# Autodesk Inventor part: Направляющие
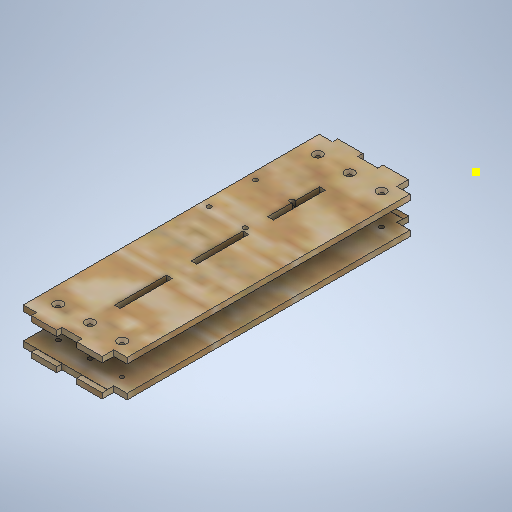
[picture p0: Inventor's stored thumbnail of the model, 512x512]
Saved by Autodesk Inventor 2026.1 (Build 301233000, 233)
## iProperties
Created: 2025-12
Part Number: Направляющие
Material: Типовые
Document SubType Name: Modeling
Designer: Yury Melnikov
Density: 1 g/cm^3
Appearance: По умолчанию
Author: Yury Melnikov
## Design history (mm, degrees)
sketch "Эскиз1"
  geometry: L1 (0, 0)-(16, 0); L2 (16, 0)-(16, -200); L3 (16, -200)-(0, -200); L4 (0, -200)-(0, 0); 1 further point
  constraints: 8 end point, 2 parallel, 1 coincident, 1 horizontal, 1 perpendicular
  dimensions: "d0" = 16 distance of L2.end L3.end; "d1" = 200 distance of L1.end L2.end
extrude "Выдавливание1" new body sketch "Эскиз1" distance "d2" = 200; taper "d3" = 0 deg
sketch "Эскиз2"
  geometry: 1 further point
sketch "Эскиз3"
  geometry: L1 (0, 0)-(0, -200) reference; L2 (-16, -200)-(-16, 0) reference; L3 (-28.3, -33.725)-(12.3, -10.284); L4 (12.3, -10.284)-(12.3, -57.165); L5 (12.3, -57.165)-(-28.3, -33.725); C1 r 12.3 at (-28.3, -33.725); C2 r 12.3 at (12.3, -10.284); C3 r 12.3 at (12.3, -57.165); 1 further point
  constraints: 6 end point, 3 centre point, 3 coincident, 2 equal radius, 2 tangent, 1 vertical, 7 other
  dimensions: "d4" = 24.6 diameter of C2
extrude "Выдавливание2" new body sketch "Эскиз3" distance "d5" = 11; taper "d6" = 0 deg
sketch "Эскиз4"
  geometry: C1 r 12.3 at (0, 0) reference; C2 r 12.3 at (40.6, 23.44) reference; C3 r 12.3 at (40.6, -23.44) reference; C4 r 4 at (0, 0); C5 r 4 at (40.6, 23.44); C6 r 4 at (40.6, -23.44); 1 further point
  constraints: 3 centre point, 3 coincident, 2 equal radius
  dimensions: "d7" = 8 diameter of C5
extrude "Выдавливание3" join sketch "Эскиз4" distance "d8" = 6; taper "d9" = 0 deg
sketch "Эскиз5"
  geometry: L1 (-6.15, 10.652)-(34.45, 34.093); L2 (52.9, 23.44)-(52.9, -23.44); L3 (34.45, -34.093)-(-6.15, -10.652); A1 r 12.3 centre (40.6, -23.44) between (34.45, -34.093) and (52.9, -23.44) reference; A2 r 12.3 centre (40.6, 23.44) between (52.9, 23.44) and (34.45, 34.093) reference; A3 r 12.3 centre (0, 0) between (-6.15, -10.652) and (-6.15, 10.652) reference; 1 further point
  constraints: 6 end point, 6 point on circle, 6 tangent
extrude "Выдавливание4" new body sketch "Эскиз5" distance "d10" = 4; taper "d11" = 0 deg
sketch "Эскиз6"
  geometry: L1 (0, 0)-(40.6, 23.44); L2 (40.6, 23.44)-(40.6, -23.44); L3 (40.6, -23.44)-(0, 0); L4 (35.6, 23.44)-(2.5, 4.33); L5 (2.5, -4.33)-(35.6, -23.44); L6 (43.1, -19.11)-(43.1, 19.11); L7 (38.1, 19.11)-(5, 0); L8 (5, 0)-(38.1, -19.11); L9 (38.1, -19.11)-(38.1, 19.11); C1 r 12.3 at (40.6, 23.44) reference; C2 r 12.3 at (40.6, -23.44) reference; C3 r 12.3 at (0, 0) reference; C4 r 1.6 at (0, 0); C5 r 1.6 at (40.6, 23.44); C6 r 1.6 at (40.6, -23.44); A1 r 5 centre (40.6, 23.44) between (43.1, 19.11) and (35.6, 23.44); A2 r 5 centre (0, 0) between (2.5, 4.33) and (2.5, -4.33); A3 r 5 centre (40.6, -23.44) between (35.6, -23.44) and (43.1, -19.11); 3 further points
  constraints: 18 end point, 8 coincident, 6 centre point, 6 point on circle, 2 equal length, 2 equal radius, 2 parallel, 13 other
  dimensions: "d12" = 2.5 distance between parallel lines of L1 L7; "d13" = 2.5 distance between parallel lines of L1 L4 (= d12); "d14" = 3.2 diameter of C4 (derived); "d15" = 3.2 diameter of C5 (derived); "d16" = 3.2 diameter of C6
extrude "Выдавливание5" join sketch "Эскиз6" distance "d17" = 5; taper "d18" = 0 deg
sketch "Эскиз7"
  geometry: C1 r 1.6 at (40.6, 23.44) reference; C2 r 1.6 at (0, 0) reference; C3 r 1.6 at (40.6, -23.44) reference; 1 further point
  node "Спроецированная петля5"
  node "Спроецированная петля6"
  node "Спроецированная петля7"
fillet "Сопряжение1" dims "d19" = 5
chamfer "Фаска1" distance "d20" = 2; stored, may be unused: second distance "d21" = 2, angle "d22" = 45 deg
extrude "Выдавливание6" cut sketch "Эскиз7" distance "d23" = 5; taper "d24" = 0 deg
sketch "Эскиз8"
  geometry: L1 (4.478, 5.472)-(33.622, 22.298) reference; L2 (43.1, 16.826)-(43.1, -16.826) reference; L3 (33.622, -22.298)-(4.478, -5.472) reference; L4 (34.45, 34.093)-(-6.15, 10.652) reference; L5 (-6.15, -10.652)-(34.45, -34.093) reference; L6 (52.9, -23.44)-(52.9, 23.44) reference; L7 (30, -82.992)-(34, -82.992); L8 (28.3, 33.725)-(28.3, -166.275) reference; L9 (142.9, -11.74)-(142.9, -38.74); L10 (139.9, -41.74)-(46.638, -41.74); L11 (35.571, -38.399)-(-6.806, -10.245); L12 (34.45, 34.093)-(-6.15, 10.652) reference; L13 (-6.15, 10.652)-(32.359, 35.974); L14 (141.217, -9.045)-(47.187, 36.917); A1 r 5 centre (1.978, -9.802) between (4.478, -5.472) and (0.989, -4.901) reference; A2 r 5 centre (0, 0) between (0.989, 4.901) and (0.989, -4.901) reference; A3 r 5 centre (1.978, 9.802) between (0.989, 4.901) and (4.478, 5.472) reference; A4 r 5 centre (31.122, 26.628) between (33.622, 22.298) and (35.861, 25.034) reference; A5 r 5 centre (40.6, 23.44) between (44.35, 20.133) and (35.861, 25.034) reference; A6 r 5 centre (48.1, 16.826) between (44.35, 20.133) and (43.1, 16.826) reference; A7 r 5 centre (48.1, -16.826) between (43.1, -16.826) and (44.35, -20.133) reference; A8 r 5 centre (40.6, -23.44) between (35.861, -25.034) and (44.35, -20.133) reference; A9 r 5 centre (31.122, -26.628) between (35.861, -25.034) and (33.622, -22.298) reference; A10 r 12.3 centre (40.6, 23.44) between (52.9, 23.44) and (34.45, 34.093) reference; A11 r 12.3 centre (0, 0) between (-6.15, 10.652) and (-6.15, -10.652) reference; A12 r 12.3 centre (40.6, -23.44) between (34.45, -34.093) and (52.9, -23.44) reference; A13 r 12.3 centre (0, 0) between (-6.15, 10.652) and (-6.15, -10.652) reference; A14 r 12.3 centre (40.6, 23.44) between (52.9, 23.44) and (34.45, 34.093) reference; A15 r 20 centre (46.638, -21.74) between (35.571, -38.399) and (46.638, -41.74); A16 r 3 centre (139.9, -11.74) between (142.9, -11.74) and (141.217, -9.045); A17 r 3 centre (139.9, -38.74) between (139.9, -41.74) and (142.9, -38.74); A18 r 15 centre (40.6, 23.44) between (26.541, 18.21) and (28.3, 14.855); A19 r 15 centre (40.6, 23.44) between (47.187, 36.917) and (32.359, 35.974); 6 further points
  constraints: 14 point on circle, 12 end point, 9 tangent, 7 point on line, 5 centre point, 1 coincident, 1 horizontal, 1 vertical, 1 vertical alignment
  dimensions: "d40" = 8 distance of point (142.9, -33.74) point (142.9, -41.74); "d41" = 90 distance from line of point (142.9, -41.74) L6; "d42" = 6 distance edge to line of A12 L10; "d43" = 20 radius of A15; "d44" = 3 radius of A16; "d45" = 3 radius of A17 (= d44); "d61" = 15 radius of A19; "d62" = 30 distance from line of L10 L9.start
extrude "Выдавливание7" new body sketch "Эскиз8" distance "d26" = 4; taper "d27" = 0 deg
node "РабПлоскость1"
sketch "Эскиз11"
  geometry: L1 (-6.806, -10.245)-(35.571, -38.399) reference; L2 (46.638, -41.74)-(139.9, -41.74) reference; L3 (142.9, -38.74)-(142.9, -11.74) reference; L4 (33.622, -22.298)-(4.478, -5.472) reference; L5 (4.478, 5.472)-(33.622, 22.298) reference; L6 (43.1, 16.826)-(43.1, -16.826) reference; L7 (30.967, -35.34)-(142.9, -35.34); L8 (37.92, -39.74)-(142.728, -39.74); L9 (77.92, -35.34)-(97.92, -35.34); L10 (97.92, -35.34)-(97.92, -39.74); L11 (97.92, -39.74)-(77.92, -39.74); L12 (77.92, -39.74)-(77.92, -35.34); L13 (112.9, -35.34)-(132.9, -35.34); L14 (132.9, -35.34)-(132.9, -39.74); L15 (132.9, -39.74)-(112.9, -39.74); L16 (112.9, -39.74)-(112.9, -35.34); L17 (32.359, 35.974)-(-6.15, 10.652) reference; L18 (141.217, -9.045)-(47.187, 36.917) reference; A1 r 12.3 centre (0, 0) between (-6.15, 10.652) and (-6.806, -10.245) reference; A2 r 20 centre (46.638, -21.74) between (35.571, -38.399) and (46.638, -41.74) reference; A3 r 3 centre (139.9, -38.74) between (139.9, -41.74) and (142.9, -38.74) reference; A4 r 3 centre (139.9, -11.74) between (142.9, -11.74) and (141.217, -9.045) reference; A5 r 5 centre (1.978, -9.802) between (4.478, -5.472) and (0.989, -4.901) reference; A6 r 5 centre (0, 0) between (0.989, 4.901) and (0.989, -4.901) reference; A7 r 5 centre (1.978, 9.802) between (0.989, 4.901) and (4.478, 5.472) reference; A8 r 5 centre (31.122, 26.628) between (33.622, 22.298) and (35.861, 25.034) reference; A9 r 5 centre (40.6, 23.44) between (44.35, 20.133) and (35.861, 25.034) reference; A10 r 5 centre (48.1, 16.826) between (44.35, 20.133) and (43.1, 16.826) reference; A11 r 5 centre (48.1, -16.826) between (43.1, -16.826) and (44.35, -20.133) reference; A12 r 5 centre (40.6, -23.44) between (35.861, -25.034) and (44.35, -20.133) reference; A13 r 5 centre (31.122, -26.628) between (35.861, -25.034) and (33.622, -22.298) reference; A14 r 15 centre (40.6, 23.44) between (47.187, 36.917) and (32.359, 35.974) reference; 1 further point
  constraints: 20 end point, 6 point on line, 4 horizontal, 4 parallel, 2 perpendicular, 2 point on circle
  dimensions: "d47" = 4.4 distance between parallel lines of L8 L7; "d48" = 2 distance between parallel lines of L2 L8; "d49" = 20 distance between parallel lines of L12 L10; "d50" = 20 distance between parallel lines of L14 L16; "d51" = 10 distance between parallel lines of L14 L3; "d52" = 40 distance from line of L8.start L12
extrude "Выдавливание9" cut sketch "Эскиз11" distance "d53" = 4; taper "d54" = 0 deg
chamfer "Фаска2" distance "d55" = 2; stored, may be unused: second distance "d56" = 2, angle "d57" = 45 deg
fillet "Сопряжение2" dims "d58" = 1
sketch "Эскиз14"
  geometry: L1 (-142.9, -35.34)-(-67.92, -35.34); L2 (-67.92, -35.34)-(-67.92, -39.74); L3 (-67.92, -39.74)-(-142.9, -39.74); L4 (-142.9, -39.74)-(-142.9, -35.34); L5 (-97.92, -35.34)-(-77.92, -35.34) reference; L6 (-77.92, -39.74)-(-97.92, -39.74) reference; L7 (-77.92, -35.34)-(-77.92, -39.74) reference; L8 (-142.9, -38.74)-(-142.9, -11.74) reference; 2 further points
  constraints: 8 end point, 3 collinear, 2 parallel, 1 horizontal, 1 midpoint, 1 perpendicular
  dimensions: "d63" = 10 distance from line of L2 point (-77.92, -37.54)
extrude "Выдавливание10" new body sketch "Эскиз14" distance "d65" = 228; taper "d66" = 0 deg
sketch "Эскиз15"
  geometry: L1 (3, 15)-(3, 11.4); L2 (3, 11.4)-(8, 6.4); L3 (8, 6.4)-(20, 6.4); L4 (20, 6.4)-(20, 3.4); L5 (20, 3.4)-(0, 3.4); L6 (0, 3.4)-(228, 3.4) reference; L7 (0, 3.4)-(0, 23); L8 (0, 23)-(20, 23); L9 (3, 15)-(8, 20); L10 (8, 20)-(20, 20); L11 (20, 20)-(20, 23); 5 further points; 1 other entity
  constraints: 20 end point, 4 equal length, 3 vertical, 2 horizontal, 2 perpendicular, 1 collinear, 1 other
  dimensions: "d67" = 3 distance of L3.end L4.end; "d76" = 3 distance between parallel lines of L7 L1 (derived); "d77" = 20 distance of L4.end L5.end; "d78" = 135 deg angle of L10 L9; "d79" = 5 horizontal distance of L1.start L9.end; "d108" = 4 distance of L7.end point (0, 27)
extrude "Выдавливание11" new body sketch "Эскиз15" stored distance "d69" = 128; taper "d70" = 0 deg
sketch "Эскиз16"
  geometry: L1 (67.92, -35.34)-(142.9, -35.34) reference; L2 (67.92, -39.74)-(67.92, -35.34) reference; L3 (142.9, -39.74)-(67.92, -39.74) reference; L4 (142.9, -35.34)-(142.9, -39.74) reference; L5 (132.9, -35.34)-(132.9, -39.74) reference; L6 (132.9, -39.74)-(112.9, -39.74) reference; L7 (112.9, -39.74)-(112.9, -35.34) reference; L8 (112.9, -35.34)-(132.9, -35.34) reference; L9 (97.92, -35.34)-(97.92, -39.74) reference; L10 (97.92, -39.74)-(77.92, -39.74) reference; L11 (77.92, -39.74)-(77.92, -35.34) reference; L12 (77.92, -35.34)-(97.92, -35.34) reference; L13 (-6.806, -10.245)-(35.571, -38.399) reference; L14 (46.638, -41.74)-(139.9, -41.74) reference; L15 (142.9, -38.74)-(142.9, -11.74) reference; L16 (141.217, -9.045)-(47.187, 36.917) reference; L17 (32.359, 35.974)-(-6.15, 10.652) reference; L18 (33.622, -22.298)-(4.478, -5.472) reference; L19 (4.478, 5.472)-(33.622, 22.298) reference; L20 (43.1, 16.826)-(43.1, -16.826) reference; L21 (97.72, -39.54)-(97.72, -35.54); L22 (97.72, -35.54)-(78.12, -35.54); L23 (78.12, -35.54)-(78.12, -39.54); L24 (78.12, -39.54)-(97.72, -39.54); L25 (113.1, -35.54)-(113.1, -39.54); L26 (113.1, -39.54)-(132.7, -39.54); L27 (132.7, -39.54)-(132.7, -35.54); L28 (132.7, -35.54)-(113.1, -35.54); A1 r 12.3 centre (0, 0) between (-6.15, 10.652) and (-6.806, -10.245) reference; A2 r 20 centre (46.638, -21.74) between (35.571, -38.399) and (46.638, -41.74) reference; A3 r 3 centre (139.9, -38.74) between (139.9, -41.74) and (142.9, -38.74) reference; A4 r 3 centre (139.9, -11.74) between (142.9, -11.74) and (141.217, -9.045) reference; A5 r 15 centre (40.6, 23.44) between (47.187, 36.917) and (32.359, 35.974) reference; A6 r 5 centre (1.978, -9.802) between (4.478, -5.472) and (0.989, -4.901) reference; A7 r 5 centre (0, 0) between (0.989, 4.901) and (0.989, -4.901) reference; A8 r 5 centre (1.978, 9.802) between (0.989, 4.901) and (4.478, 5.472) reference; A9 r 5 centre (31.122, 26.628) between (33.622, 22.298) and (35.861, 25.034) reference; A10 r 5 centre (40.6, 23.44) between (44.35, 20.133) and (35.861, 25.034) reference; A11 r 5 centre (48.1, 16.826) between (44.35, 20.133) and (43.1, 16.826) reference; A12 r 5 centre (48.1, -16.826) between (43.1, -16.826) and (44.35, -20.133) reference; A13 r 5 centre (40.6, -23.44) between (35.861, -25.034) and (44.35, -20.133) reference; A14 r 5 centre (31.122, -26.628) between (35.861, -25.034) and (33.622, -22.298) reference; 1 further point
  constraints: 16 end point, 6 other
  dimensions: "d71" = 0.2 distance between parallel lines of L9 L21; "d72" = 0.2 distance between parallel lines of L7 L25
extrude "Выдавливание12" join sketch "Эскиз16" stored distance "d73" = 228; taper "d74" = 0 deg
node "РабПлоскость2"
mirror "Зеркальное отражение2"
sketch "Эскиз17"
  geometry: L1 (15.8, 7.674)-(15.8, 4.326); L2 (15.8, 4.326)-(12.9, 2.651); L3 (12.9, 2.651)-(10, 4.326); L4 (10, 4.326)-(10, 7.674); L5 (10, 7.674)-(12.9, 9.349); L6 (12.9, 9.349)-(15.8, 7.674); L7 (12.9, 0.342)-(17.8, 3.171); L8 (17.8, 3.171)-(17.8, 8.829); L9 (17.8, 8.829)-(12.9, 11.658); L10 (12.9, 11.658)-(8, 8.829); L11 (8, 8.829)-(8, 3.171); L12 (8, 3.171)-(12.9, 0.342); L13 (0, 0)-(0, 12) reference; L14 (0, 17)-(74.98, 17) reference; L15 (32.59, 8.829)-(32.59, 3.171); L16 (34.59, 4.326)-(34.59, 7.674); L17 (37.49, 2.651)-(34.59, 4.326); L18 (37.49, 11.658)-(32.59, 8.829); L19 (32.59, 3.171)-(37.49, 0.342); L20 (34.59, 7.674)-(37.49, 9.349); L21 (40.39, 4.326)-(37.49, 2.651); L22 (40.39, 7.674)-(40.39, 4.326); L23 (37.49, 9.349)-(40.39, 7.674); L24 (37.49, 0.342)-(42.39, 3.171); L25 (42.39, 3.171)-(42.39, 8.829); L26 (42.39, 8.829)-(37.49, 11.658); L27 (57.18, 8.829)-(57.18, 3.171); L28 (59.18, 4.326)-(59.18, 7.674); L29 (62.08, 2.651)-(59.18, 4.326); L30 (62.08, 11.658)-(57.18, 8.829); L31 (57.18, 3.171)-(62.08, 0.342); L32 (59.18, 7.674)-(62.08, 9.349); L33 (64.98, 4.326)-(62.08, 2.651); L34 (64.98, 7.674)-(64.98, 4.326); L35 (62.08, 9.349)-(64.98, 7.674); L36 (62.08, 0.342)-(66.98, 3.171); L37 (66.98, 3.171)-(66.98, 8.829); L38 (66.98, 8.829)-(62.08, 11.658); L39 (74.98, 0)-(74.98, 12) reference; 11 further points
  constraints: 72 end point, 5 midpoint, 1 horizontal, 1 horizontal alignment, 1 vertical, 70 other
  dimensions: "d80" = 5.8 distance between parallel lines of L4 L1; "d82" = 2 distance from line of point (15.35, 1.756) L2; "d85" = 24.58984 distance of L10.end L15.start (derived); "d90" = 8 distance from line of point (8, 6) L13; "d157" = 8 distance of point (66.98, 6) point (74.98, 6) (derived)
extrude "Выдавливание13" join sketch "Эскиз17" distance "d92" = 2.5; taper "d93" = 0 deg
fillet "Сопряжение3" dims "d94" = 2
chamfer "Фаска3" distance "d95" = 0.8; stored, may be unused: second distance "d96" = 2, angle "d97" = 45 deg
sketch "Эскиз18"
  geometry: L1 (5.8, 3.349)-(2.9, 5.023) reference; L2 (2.9, 5.023)-(0, 3.349) reference; L3 (0, 3.349)-(0, 0) reference; L4 (0, 0)-(2.9, -1.674) reference; L5 (2.9, -1.674)-(5.8, 0) reference; L6 (5.8, 0)-(5.8, 3.349) reference; L7 (5.8, 3.349)-(5.8, 0) reference; L8 (-10, 7.674)-(64.98, 7.674) reference; C1 r 1.65 at (2.9, 1.674); C2 r 1.65 at (27.49, 1.674); C3 r 1.65 at (52.08, 1.674); C4 r 1.65 at (76.67, 1.674); 3 further points
  constraints: 4 centre point, 2 vertical alignment, 1 horizontal, 1 horizontal alignment, 1 midpoint, 6 other
  dimensions: "d98" = 3.3 diameter of C1; "d101" = 24.58984 distance of C1.centre C2.centre (derived)
extrude "Выдавливание14" cut sketch "Эскиз18" distance "d106" = 10; taper "d107" = 0 deg
node "РабПлоскость3"
mirror "Зеркальное отражение3"
sketch "Эскиз19"
  geometry: L1 (-97.72, -35.54)-(-97.72, -39.54) reference; L2 (-78.12, -35.54)-(-97.72, -35.54) reference; L3 (-78.12, -39.54)-(-78.12, -35.54) reference; L4 (-97.72, -39.54)-(-78.12, -39.54) reference; L5 (-77.92, -11.54)-(-97.92, -11.54); L6 (-97.92, -11.54)-(-97.92, -15.74); L7 (-97.92, -15.74)-(-77.92, -15.74); L8 (-77.92, -15.74)-(-77.92, -11.54); L9 (-142.9, -15.74)-(-67.92, -15.74) reference; L10 (-112.9, -11.54)-(-132.9, -11.54); L11 (-132.9, -11.54)-(-132.9, -15.74); L12 (-132.9, -15.74)-(-112.9, -15.74); L13 (-112.9, -15.74)-(-112.9, -11.54); L14 (-112.9, -39.74)-(-112.9, -35.34) reference; L15 (-132.9, -35.34)-(-132.9, -39.74) reference; L16 (-77.92, -39.74)-(-77.92, -35.34) reference; L17 (-97.92, -35.34)-(-97.92, -39.74) reference; 3 further points
  constraints: 16 end point, 6 collinear, 4 parallel, 2 horizontal, 2 perpendicular
  dimensions: "d109" = 4.2 distance of L7.end L5.start; "d110" = 4.2 distance of L12.end L10.start
extrude "Выдавливание15" cut sketch "Эскиз19" distance "d111" = 10; taper "d112" = 0 deg
sketch "Эскиз20"
  geometry: L1 (39.69, -35)-(35.29, -35); L2 (35.29, -35)-(35.29, -75); L3 (35.29, -75)-(39.69, -75); L4 (39.69, -75)-(39.69, -35); L5 (39.69, -94)-(35.29, -94); L6 (35.29, -94)-(35.29, -134); L7 (35.29, -134)-(39.69, -134); L8 (39.69, -134)-(39.69, -94); L9 (39.69, -153)-(35.29, -153); L10 (35.29, -153)-(35.29, -193); L11 (35.29, -193)-(39.69, -193); L12 (39.69, -193)-(39.69, -153); L13 (0, -20)-(74.98, -20) reference; L14 (0, 0)-(74.98, 0) reference; L15 (74.98, -228)-(0, -228) reference; 3 further points
  constraints: 24 end point, 2 midpoint, 2 parallel, 1 collinear, 1 horizontal, 1 perpendicular, 1 vertical, 1 vertical alignment, 15 other
  dimensions: "d113" = 4.4 distance of L1.start L1.end; "d116" = 59 distance of L1.start L5.start (derived); "d122" = 35 distance between parallel lines of L14 L1; "d123" = 35 distance from line of L15 L11.end; "d124" = 40 distance of L3.end L1.start
extrude "Выдавливание16" cut sketch "Эскиз20" distance "d125" = 10; taper "d126" = 0 deg
sketch "Эскиз21"
  geometry: L1 (39.69, -193)-(35.29, -193) reference; L2 (35.29, -193)-(35.29, -153) reference; L3 (35.29, -153)-(39.69, -153) reference; L4 (39.69, -153)-(39.69, -193) reference; L5 (39.69, -134)-(35.29, -134) reference; L6 (35.29, -134)-(35.29, -94) reference; L7 (35.29, -94)-(39.69, -94) reference; L8 (39.69, -94)-(39.69, -134) reference; L9 (39.69, -75)-(35.29, -75) reference; L10 (35.29, -75)-(35.29, -35) reference; L11 (35.29, -35)-(39.69, -35) reference; L12 (39.69, -35)-(39.69, -75) reference; L13 (74.98, 0)-(0, 0) reference; L14 (0, 0)-(0, -228) reference; L15 (74.98, -228)-(0, -228) reference; L16 (74.98, 0)-(74.98, -228) reference; L17 (39.59, -74.9)-(35.39, -74.9); L18 (35.39, -74.9)-(35.39, -35.1); L19 (35.39, -35.1)-(39.59, -35.1); L20 (39.59, -35.1)-(39.59, -74.9); L21 (39.59, -133.9)-(35.39, -133.9); L22 (35.39, -133.9)-(35.39, -94.1); L23 (35.39, -94.1)-(39.59, -94.1); L24 (39.59, -94.1)-(39.59, -133.9); L25 (39.59, -192.9)-(35.39, -192.9); L26 (35.39, -192.9)-(35.39, -153.1); L27 (35.39, -153.1)-(39.59, -153.1); L28 (39.59, -153.1)-(39.59, -192.9); L29 (0, -20)-(74.98, -20) reference; L30 (39.59, -20)-(35.39, -20); L31 (35.39, -20)-(35.39, -208); L32 (35.39, -208)-(39.59, -208); L33 (39.59, -208)-(39.59, -20); C1 r 1.65 at (62.08, -14) reference; C2 r 1.65 at (37.49, -14) reference; C3 r 1.65 at (12.9, -14) reference; 1 further point
  constraints: 32 end point, 2 collinear, 2 parallel, 1 horizontal, 1 perpendicular, 1 point on line, 9 other
  dimensions: "d127" = 0.1 distance between parallel lines of L12 L20; "d128" = 0.1 distance between parallel lines of L8 L24; "d129" = 0.1 distance between parallel lines of L4 L28; "d130" = 20 distance between parallel lines of L15 L32
extrude "Выдавливание17" new body sketch "Эскиз21" stored distance "d131" = 10; taper "d132" = 0 deg
sketch "Эскиз22"
  geometry: L1 (39.59, -20)-(35.39, -20); L2 (35.39, -20)-(35.39, -208); L3 (35.39, -208)-(39.59, -208); L4 (39.59, -208)-(39.59, -20); L5 (0, -20)-(74.98, -20) reference; L6 (74.98, -228)-(0, -228) reference; 3 further points
  constraints: 8 end point, 2 parallel, 2 point on line, 1 collinear, 1 horizontal, 1 perpendicular
  dimensions: "d133" = 20 distance between parallel lines of L6 L3
extrude "Выдавливание18" join sketch "Эскиз22" stored distance "d134" = 10; taper "d135" = 0 deg
node "РабПлоскость4"
mirror "Зеркальное отражение4"
sketch "Эскиз23"
  geometry: L1 (-112.9, -15.74)-(-132.9, -15.74) reference; L2 (-132.9, -15.74)-(-132.9, -11.54) reference; L3 (-132.9, -11.54)-(-112.9, -11.54) reference; L4 (-112.9, -11.54)-(-112.9, -15.74) reference; L5 (-77.92, -15.74)-(-97.92, -15.74) reference; L6 (-97.92, -15.74)-(-97.92, -11.54) reference; L7 (-97.92, -11.54)-(-77.92, -11.54) reference; L8 (-77.92, -11.54)-(-77.92, -15.74) reference; L9 (-132.9, -39.74)-(-132.9, -35.34) reference; L10 (-132.9, -35.34)-(-112.9, -35.34) reference; L11 (-112.9, -35.34)-(-112.9, -39.74) reference; L12 (-112.9, -39.74)-(-132.9, -39.74) reference; L13 (-97.92, -39.74)-(-97.92, -35.34) reference; L14 (-97.92, -35.34)-(-77.92, -35.34) reference; L15 (-77.92, -35.34)-(-77.92, -39.74) reference; L16 (-77.92, -39.74)-(-97.92, -39.74) reference; L17 (-32.359, 35.974)-(6.15, 10.652) reference; L18 (-141.217, -9.045)-(-47.187, 36.917) reference; L19 (-142.9, -38.74)-(-142.9, -11.74) reference; L20 (-46.638, -41.74)-(-139.9, -41.74) reference; L21 (6.806, -10.245)-(-35.571, -38.399) reference; L22 (-33.622, -22.298)-(-4.478, -5.472) reference; L23 (-43.1, 16.826)-(-43.1, -16.826) reference; L24 (-4.478, 5.472)-(-33.622, 22.298) reference; C1 r 1.65 at (-45.173, -38.366); C2 r 1.65 at (-57.173, -38.366); C3 r 12.3 at (-40.6, -23.44) reference; C4 r 3.31 at (-45.173, -38.366); A1 r 12.3 centre (0, 0) between (6.806, -10.245) and (6.15, 10.652) reference; A2 r 15 centre (-40.6, 23.44) between (-32.359, 35.974) and (-47.187, 36.917) reference; A3 r 3 centre (-139.9, -11.74) between (-141.217, -9.045) and (-142.9, -11.74) reference; A4 r 3 centre (-139.9, -38.74) between (-142.9, -38.74) and (-139.9, -41.74) reference; A5 r 20 centre (-46.638, -21.74) between (-46.638, -41.74) and (-35.571, -38.399) reference; A6 r 5 centre (-31.122, -26.628) between (-33.622, -22.298) and (-35.861, -25.034) reference; A7 r 5 centre (-40.6, -23.44) between (-44.35, -20.133) and (-35.861, -25.034) reference; A8 r 5 centre (-48.1, -16.826) between (-44.35, -20.133) and (-43.1, -16.826) reference; A9 r 5 centre (-48.1, 16.826) between (-43.1, 16.826) and (-44.35, 20.133) reference; A10 r 5 centre (-40.6, 23.44) between (-35.861, 25.034) and (-44.35, 20.133) reference; A11 r 5 centre (-31.122, 26.628) between (-35.861, 25.034) and (-33.622, 22.298) reference; A12 r 5 centre (-1.978, 9.802) between (-4.478, 5.472) and (-0.989, 4.901) reference; A13 r 5 centre (0, 0) between (-0.989, -4.901) and (-0.989, 4.901) reference; A14 r 5 centre (-1.978, -9.802) between (-0.989, -4.901) and (-4.478, -5.472) reference; 1 further point
  constraints: 3 centre point, 2 tangent, 1 coincident, 1 equal radius, 1 horizontal alignment
  dimensions: "d136" = 3.3 diameter of C2; "d137" = 12 distance of C1.centre C2.centre
extrude "Выдавливание19" cut sketch "Эскиз23" distance "d138" = 10; taper "d139" = 0 deg
sketch "Эскиз24"
  geometry: C1 r 4 at (0, 0) reference; C2 r 4 at (40.6, 23.44) reference; C3 r 4 at (40.6, -23.44) reference; C4 r 2.5 at (0, 0); C5 r 2.5 at (40.6, 23.44); C6 r 2.5 at (40.6, -23.44); C7 r 5.5 at (40.6, 23.44); C8 r 5.5 at (0, 0); C9 r 5.5 at (40.6, -23.44); 1 further point
  constraints: 6 centre point, 2 coincident, 1 concentric
  dimensions: "d140" = 5 diameter of C4; "d141" = 5 diameter of C5; "d142" = 5 diameter of C6; "d143" = 3 radial gap between concentric circles of C5 C7; "d144" = 3 radial gap between concentric circles of C4 C8; "d145" = 3 radial gap between concentric circles of C6 C9
extrude "Выдавливание20" join sketch "Эскиз24" stored distance "d146" = 10; taper "d147" = 0 deg
sketch "Эскиз25"
  geometry: C1 r 5.5 at (0, 0) reference; C2 r 5.5 at (40.6, -23.44) reference; C3 r 5.5 at (40.6, 23.44) reference; C4 r 2.5 at (0, 0); C5 r 2.5 at (40.6, 23.44); C6 r 2.5 at (40.6, -23.44); 1 further point
  constraints: 3 centre point, 3 coincident, 2 equal radius
  dimensions: "d148" = 5 diameter of C4
extrude "Выдавливание21" cut sketch "Эскиз25" distance "d149" = 30; taper "d150" = 0 deg
chamfer "Фаска4" distance "d151" = 4; stored, may be unused: second distance "d152" = 2, angle "d153" = 45 deg
sketch "Эскиз26"
  geometry: L1 (39.69, -193)-(35.29, -193) reference; L2 (35.29, -193)-(35.29, -153) reference; L3 (35.29, -153)-(39.69, -153) reference; L4 (39.69, -153)-(39.69, -193) reference; L5 (39.69, -134)-(35.29, -134) reference; L6 (35.29, -134)-(35.29, -94) reference; L7 (35.29, -94)-(39.69, -94) reference; L8 (39.69, -94)-(39.69, -134) reference; L9 (39.69, -75)-(35.29, -75) reference; L10 (35.29, -75)-(35.29, -35) reference; L11 (35.29, -35)-(39.69, -35) reference; L12 (39.69, -35)-(39.69, -75) reference; L13 (74.98, 0)-(0, 0) reference; L14 (0, 0)-(0, -228) reference; L15 (74.98, -228)-(0, -228) reference; L16 (74.98, 0)-(74.98, -228) reference; L17 (74.98, 0)-(64.78, 0); L18 (64.78, 0)-(64.78, -5); L19 (64.78, -5)-(74.98, -5); L20 (74.98, -5)-(74.98, 0); L21 (64.78, 0)-(64.78, 4) reference; L22 (74.98, -228)-(64.78, -228); L23 (64.78, -228)-(64.78, -223); L24 (64.78, -223)-(74.98, -223); L25 (74.98, -223)-(74.98, -228); L26 (64.78, -228)-(64.78, -232) reference; C1 r 1.65 at (62.08, -14) reference; C2 r 1.65 at (37.49, -14) reference; C3 r 1.65 at (12.9, -14) reference; 5 further points
  constraints: 16 end point, 4 parallel, 3 collinear, 2 horizontal, 2 perpendicular
  dimensions: "d154" = 5 distance of L18.end L17.end
extrude "Выдавливание22" cut sketch "Эскиз26" distance "d155" = 30; taper "d156" = 0 deg
feature "Толщина1" dims "d158" = 0.2, "d159" = 0.2
sketch "Эскиз27"
  geometry: L1 (-16.475, -18.345)-(-16.475, 18.345); L2 (-16.475, 18.345)-(-48.25, 0); L3 (-48.25, 0)-(-16.475, -18.345); L4 (-52.9, -23.44)-(-52.9, 23.44) reference; L5 (6.15, -10.652)-(-34.45, -34.093) reference; L6 (-34.45, 34.093)-(6.15, 10.652) reference; C1 r 1.65 at (-16.475, 18.345); C2 r 1.65 at (-16.475, -18.345); C3 r 1.65 at (-48.25, 0); 1 further point
  constraints: 6 end point, 3 centre point, 2 equal length, 2 equal radius, 1 vertical
  dimensions: "d160" = 3.3 diameter of C2; "d161" = 3 distance edge to line of C3 L4; "d162" = 3 distance edge to line of C2 L5; "d163" = 3 distance edge to line of C1 L6
extrude "Выдавливание23" cut sketch "Эскиз27" distance "d164" = 20; taper "d165" = 0 deg
chamfer "Фаска5" distance "d166" = 2; stored, may be unused: second distance "d167" = 2, angle "d168" = 45 deg
sketch "Эскиз28"
  geometry: L1 (14.517, 4.6)-(16.133, 1.8); L2 (16.133, 1.8)-(14.517, -1); L3 (14.517, -1)-(11.283, -1); L4 (11.283, -1)-(9.667, 1.8); L5 (9.667, 1.8)-(11.283, 4.6); L6 (11.283, 4.6)-(14.517, 4.6); L7 (0, 0)-(0, 3.6) reference; L8 (13.9, 6.1)-(11.9, 6.1) reference; L9 (39.106, 4.6)-(40.723, 1.8); L10 (40.723, 1.8)-(39.106, -1); L11 (39.106, -1)-(35.873, -1); L12 (35.873, -1)-(34.257, 1.8); L13 (34.257, 1.8)-(35.873, 4.6); L14 (35.873, 4.6)-(39.106, 4.6); L15 (63.696, 4.6)-(65.313, 1.8); L16 (65.313, 1.8)-(63.696, -1); L17 (63.696, -1)-(60.463, -1); L18 (60.463, -1)-(58.847, 1.8); L19 (58.847, 1.8)-(60.463, 4.6); L20 (60.463, 4.6)-(63.696, 4.6); L21 (38.49, 6.1)-(36.49, 6.1) reference; L22 (17.981, 1.8)-(15.44, 6.2); L23 (15.44, 6.2)-(10.36, 6.2); L24 (10.36, 6.2)-(7.819, 1.8); L25 (7.819, 1.8)-(10.36, -2.6); L26 (10.36, -2.6)-(15.44, -2.6); L27 (15.44, -2.6)-(17.981, 1.8); L28 (34.949, 6.2)-(32.409, 1.8); L29 (32.409, 1.8)-(34.949, -2.6); L30 (34.949, -2.6)-(40.03, -2.6); L31 (40.03, -2.6)-(42.571, 1.8); L32 (42.571, 1.8)-(40.03, 6.2); L33 (40.03, 6.2)-(34.949, 6.2); L34 (59.539, 6.2)-(56.999, 1.8); L35 (56.999, 1.8)-(59.539, -2.6); L36 (59.539, -2.6)-(64.62, -2.6); L37 (64.62, -2.6)-(67.16, 1.8); L38 (67.16, 1.8)-(64.62, 6.2); L39 (64.62, 6.2)-(59.539, 6.2); 7 further points
  constraints: 72 end point, 3 midpoint, 2 horizontal, 2 vertical alignment, 1 collinear, 1 horizontal alignment, 53 other
  dimensions: "d169" = 5.6 distance between parallel lines of L3 L6; "d172" = 24.58984 distance of point (12.9, 1.8) point (37.49, 1.8) (derived); "d177" = 1.6 distance between parallel lines of L1 L22; "d178" = 1.6 distance between parallel lines of L13 L28; "d179" = 1.6 distance between parallel lines of L19 L34
extrude "Выдавливание24" join sketch "Эскиз28" distance "d180" = 3; taper "d181" = 0 deg
sketch "Эскиз29"
  geometry: L1 (15.44, 6.2)-(10.36, 6.2) reference; L2 (10.36, 6.2)-(7.819, 1.8) reference; L3 (7.819, 1.8)-(10.36, -2.6) reference; L4 (10.36, -2.6)-(15.44, -2.6) reference; L5 (15.44, -2.6)-(17.981, 1.8) reference; L6 (17.981, 1.8)-(15.44, 6.2) reference; L7 (14.517, 4.6)-(16.133, 1.8) reference; L8 (16.133, 1.8)-(14.517, -1) reference; L9 (14.517, -1)-(11.283, -1) reference; L10 (11.283, -1)-(9.667, 1.8) reference; L11 (9.667, 1.8)-(11.283, 4.6) reference; L12 (11.283, 4.6)-(14.517, 4.6) reference; L13 (32.409, 1.8)-(34.949, -2.6) reference; L14 (34.949, -2.6)-(40.03, -2.6) reference; L15 (40.03, -2.6)-(42.571, 1.8) reference; L16 (42.571, 1.8)-(40.03, 6.2) reference; L17 (40.03, 6.2)-(34.949, 6.2) reference; L18 (34.949, 6.2)-(32.409, 1.8) reference; L19 (39.106, 4.6)-(40.723, 1.8) reference; L20 (40.723, 1.8)-(39.106, -1) reference; L21 (39.106, -1)-(35.873, -1) reference; L22 (35.873, -1)-(34.257, 1.8) reference; L23 (34.257, 1.8)-(35.873, 4.6) reference; L24 (35.873, 4.6)-(39.106, 4.6) reference; L25 (56.999, 1.8)-(59.539, -2.6) reference; L26 (59.539, -2.6)-(64.62, -2.6) reference; L27 (64.62, -2.6)-(67.16, 1.8) reference; L28 (67.16, 1.8)-(64.62, 6.2) reference; L29 (64.62, 6.2)-(59.539, 6.2) reference; L30 (59.539, 6.2)-(56.999, 1.8) reference; L31 (63.696, 4.6)-(65.313, 1.8) reference; L32 (65.313, 1.8)-(63.696, -1) reference; L33 (63.696, -1)-(60.463, -1) reference; L34 (60.463, -1)-(58.847, 1.8) reference; L35 (58.847, 1.8)-(60.463, 4.6) reference; L36 (60.463, 4.6)-(63.696, 4.6) reference; 1 further point
extrude "Выдавливание25" cut sketch "Эскиз29" stored distance "d182" = 3; taper "d183" = 0 deg
sketch "Эскиз30"
  geometry: L1 (-24.59, 5.6)-(-26.206, 2.8) reference; L2 (-24.59, 0)-(-26.206, 2.8) reference; L3 (-21.357, 0)-(-24.59, 0) reference; L4 (-21.357, 0)-(-19.74, 2.8) reference; L5 (-19.74, 2.8)-(-21.357, 5.6) reference; L6 (-24.59, 5.6)-(-21.357, 5.6) reference; L7 (0, 5.6)-(-1.617, 2.8) reference; L8 (0, 0)-(-1.617, 2.8) reference; L9 (3.233, 0)-(0, 0) reference; L10 (3.233, 0)-(4.85, 2.8) reference; L11 (4.85, 2.8)-(3.233, 5.6) reference; L12 (0, 5.6)-(3.233, 5.6) reference; L13 (24.59, 5.6)-(22.973, 2.8) reference; L14 (24.59, 0)-(22.973, 2.8) reference; L15 (27.823, 0)-(24.59, 0) reference; L16 (27.823, 0)-(29.44, 2.8) reference; L17 (29.44, 2.8)-(27.823, 5.6) reference; L18 (24.59, 5.6)-(27.823, 5.6) reference; L19 (24.59, 5.6)-(27.823, 5.6) reference; L20 (0, 5.6)-(3.233, 5.6) reference; L21 (-24.59, 5.6)-(-21.357, 5.6) reference; C1 r 1.65 at (-22.973, 2.8); C2 r 1.65 at (1.617, 2.8); C3 r 1.65 at (26.206, 2.8); 4 further points
  constraints: 3 centre point, 3 horizontal alignment, 3 midpoint, 3 vertical alignment, 2 equal radius
  dimensions: "d184" = 3.3 diameter of C2
extrude "Выдавливание26" cut sketch "Эскиз30" distance "d185" = 10; taper "d186" = 0 deg
chamfer "Фаска6" distance "d187" = 0.7; stored, may be unused: second distance "d188" = 2, angle "d189" = 45 deg
fillet "Сопряжение4" dims "d190" = 1
sketch "Эскиз31"
  geometry: L1 (19.6, -236)-(0, -236) reference; L2 (0, -232)-(0, -236) reference; L3 (19.6, -232)-(0, -232) reference; L4 (19.6, -232)-(19.6, -236) reference; L5 (54.58, -236)-(34.98, -236) reference; L6 (34.98, -232)-(34.98, -236) reference; L7 (54.58, -232)-(34.98, -232) reference; L8 (54.58, -232)-(54.58, -236) reference; L9 (19.6, 0)-(0, 0) reference; L10 (19.6, -4)-(19.6, 0) reference; L11 (0, -4)-(19.6, -4) reference; L12 (0, -4)-(0, 0) reference; L13 (54.58, 0)-(34.98, 0) reference; L14 (54.58, -4)-(54.58, 0) reference; L15 (34.98, -4)-(54.58, -4) reference; L16 (34.98, -4)-(34.98, 0) reference; 1 further point
extrude "Выдавливание27" join sketch "Эскиз31" stored distance "d191" = 10; taper "d192" = 0 deg
mirror "Зеркальное отражение5"
chamfer "Фаска7" distance "d193" = 0.5; stored, may be unused: second distance "d194" = 2, angle "d195" = 45 deg
sketch "Эскиз32"
  geometry: L1 (-52.9, -23.44)-(-51.9, -23.44) reference; L2 (-52.9, -23.44)-(-52.9, 23.44) reference; L3 (6.15, -10.652)-(-34.45, -34.093) reference; L4 (-34.45, 34.093)-(6.15, 10.652) reference; C1 r 3.65 at (-16.475, -18.345) reference; C2 r 1.6 at (-40.6, 23.44) reference; C3 r 1.6 at (-40.6, -23.44) reference; C4 r 1.6 at (0, 0) reference; C5 r 3.65 at (-16.475, 18.345) reference; C6 r 3.65 at (-48.25, 0) reference; A1 r 35 centre (-27.005, 0.107) between (-52.9, -23.44) and (-34.45, -34.093); A2 r 12.3 centre (-40.6, 23.44) between (-34.45, 34.093) and (-52.9, 23.44) reference; A3 r 12.3 centre (-40.6, -23.44) between (-52.9, -23.44) and (-34.45, -34.093) reference; A4 r 12.3 centre (0, 0) between (6.15, -10.652) and (6.15, 10.652) reference; 3 further points
  constraints: 2 point on circle, 1 centre point
  dimensions: "d196" = 35 radius of A1
extrude "Выдавливание28" cut sketch "Эскиз32" distance "d197" = 10; taper "d198" = 0 deg
fillet "Сопряжение5" dims "d199" = 10
chamfer "Фаска8" distance "d200" = 1; stored, may be unused: second distance "d201" = 2, angle "d202" = 45 deg
sketch "Эскиз33"
  geometry: C1 r 1.6 at (-40.6, 23.44) reference; C2 r 1.65 at (-40.6, 23.44); C3 r 4.05 at (-40.6, 23.44); 1 further point
  constraints: 2 centre point, 1 coincident
  dimensions: "d203" = 3.3 diameter of C2; "d204" = 2.4 radial gap between concentric circles of C2 C3
extrude "Выдавливание29" new body sketch "Эскиз33" distance "d205" = 5; taper "d206" = 0 deg
sketch "Эскиз34"
  geometry: C1 r 1.65 at (0, 0) reference; C2 r 2.45 at (0, 0); 1 further point
  constraints: 1 centre point
  dimensions: "d207" = 0.8 radial gap between concentric circles of C1 C2
extrude "Выдавливание30" join sketch "Эскиз34" distance "d208" = 1; taper "d209" = 0 deg
chamfer "Фаска10" distance "d213" = 0.5; stored, may be unused: second distance "d214" = 1.6, angle "d215" = 45 deg
sketch "Эскиз35"
  geometry: C1 r 12.3 at (0, 0) reference; C2 r 1.65 at (0, 0); 1 further point
  constraints: 1 centre point, 1 coincident
  dimensions: "d216" = 3.3 diameter of C2
extrude "Выдавливание31" new body sketch "Эскиз35" distance "d217" = 11; taper "d218" = 0 deg
sketch "Эскиз36"
  geometry: L1 (-2.8, -1.617)-(-2.8, 1.617); L2 (-2.8, 1.617)-(0, 3.233); L3 (0, 3.233)-(2.8, 1.617); L4 (2.8, 1.617)-(2.8, -1.617); L5 (2.8, -1.617)-(0, -3.233); L6 (0, -3.233)-(-2.8, -1.617); C1 r 1.65 at (0, 0) reference; 2 further points
  constraints: 12 end point, 1 coincident, 1 vertical, 13 other
  dimensions: "d219" = 5.6 distance between parallel lines of L4 L1
extrude "Выдавливание32" cut sketch "Эскиз36" distance "d220" = 5; taper "d221" = 0 deg
fillet "Сопряжение6" dims "d225" = 1
sketch "Эскиз38"
  geometry: C1 r 1.65 at (0, 0) reference; C2 r 3.9 at (0, 0); 1 further point
  constraints: 1 centre point, 1 coincident
  dimensions: "d230" = 7.8 diameter of C2
extrude "Выдавливание33" cut sketch "Эскиз38" stored distance "d231" = 4; taper "d232" = 0 deg
chamfer "Фаска12" distance "d233" = 0.4; stored, may be unused: second distance "d234" = 1.6, angle "d235" = 45 deg
sketch "Эскиз40"
  geometry: C1 r 1.6 at (0, 0) reference; C2 r 1.6 at (-40.6, -23.44) reference; 3 further points
  constraints: 2 coincident
feature "Массив по эскизу1" sketch "Эскиз40"
sketch "Эскиз41"
  geometry: C1 r 1.6 at (0, 0) reference; C2 r 1.6 at (-40.6, -23.44) reference; 3 further points
  constraints: 2 coincident
feature "Массив по эскизу2" sketch "Эскиз41"
mirror "Зеркальное отражение6"
mirror "Зеркальное отражение7"
mirror "Зеркальное отражение8"
mirror "Зеркальное отражение9"
mirror "Зеркальное отражение10"
node "РабПлоскость6"
mirror "Зеркальное отражение11"
sketch "Эскиз42"
  geometry: L1 (4.2, -55)-(-23.8, -55); L2 (-23.8, -55)-(-23.8, -90.855); L3 (-23.8, -90.855)-(4.2, -90.855); L4 (4.2, -90.855)-(4.2, -55); L5 (-29.8, 0)-(-29.8, -228) reference; L6 (9.89, -75)-(5.49, -75) reference; C1 r 1.75 at (4.2, -55); C2 r 1.75 at (4.2, -90.855); C3 r 1.75 at (-23.8, -55); C4 r 1.75 at (-23.8, -90.855); 1 further point
  constraints: 8 end point, 4 centre point, 2 horizontal, 2 parallel, 1 perpendicular, 1 vertical, 6 other
  dimensions: "d237" = 35.855 distance of L1.end L2.end; "d238" = 28 distance of L1.start L1.end; "d239" = 3.5 diameter of C1; "d240" = 6 distance from line of L5 L1.end; "d241" = 20 distance from line of L1.start L6; "d244" = 35.855 distance of L1.start C2.centre (derived); "d247" = 28 distance of L1.start C3.centre (derived)
extrude "Выдавливание34" cut sketch "Эскиз42" distance "d250" = 10; taper "d251" = 0 deg
chamfer "Фаска13" distance "d252" = 2; stored, may be unused: second distance "d253" = 2, angle "d254" = 45 deg
sketch "Эскиз43"
  geometry: L1 (45.18, -5)-(45.18, -223) reference; L2 (-29.8, 0)-(-29.8, -228) reference; L3 (45.18, -116.855)-(-29.8, -116.855); L4 (-29.8, -116.855)-(-29.8, -227); L5 (-29.8, -227)-(45.18, -227); L6 (45.18, -227)-(45.18, -116.855); L7 (-28.117, -228)-(65.913, -228) reference; C1 r 1.75 at (-23.8, -90.855) reference; 1 further point
  constraints: 8 end point, 2 parallel, 2 point on line, 1 horizontal, 1 perpendicular
  dimensions: "d255" = 1 distance between parallel lines of L7 L5; "d256" = 26 distance from line of C1.centre L3
node "РабПлоскость7"
sketch "Эскиз44"
  geometry: L1 (-33.508, -130.428)-(-87.508, -130.428); L2 (-87.508, -130.428)-(-87.508, -214.428); L3 (-87.508, -214.428)-(-33.508, -214.428); L4 (-33.508, -214.428)-(-33.508, -130.428); L5 (-5.181, -116.855)-(-5.181, -228); L6 (-29.8, -227)-(45.18, -227) reference; L7 (45.18, -116.855)-(-29.8, -116.855) reference; L8 (-28.117, -228)-(65.913, -228) reference; L9 (60.2, -208)-(60.2, -217) reference; L10 (54.2, -122.428)-(-28.508, -122.428); L11 (-28.508, -122.428)-(-28.508, -222.428); L12 (-28.508, -222.428)-(54.2, -222.427); L13 (54.2, -222.427)-(54.2, -122.428); L14 (-29.8, -116.855)-(-29.8, -227); L15 (45.18, -227)-(45.18, -116.855); L16 (45.18, -116.855)-(56.2, -119.427); L17 (56.2, -119.427)-(56.2, -224.427); L18 (45.18, -5)-(45.18, -223) reference; L19 (56.2, -224.427)-(45.18, -227); L20 (-29.8, -116.855)-(-89.508, -128.428); L21 (-89.508, -128.428)-(-89.508, -215.428); L22 (-89.508, -215.428)-(-29.8, -227); 5 further points
  constraints: 34 end point, 6 parallel, 4 midpoint, 3 vertical, 2 equal length, 2 horizontal, 2 horizontal alignment, 2 perpendicular, 2 point on line
  dimensions: "d258" = 54 distance of L3.end L2.end; "d259" = 84 distance of L2.end L1.end; "d261" = 82.708 distance of L12.end L11.end; "d262" = 100 distance of L11.end L10.end; "d263" = 6 distance between parallel lines of L9 L13; "d264" = 5 distance between parallel lines of L11 L4; "d265" = 2 distance between parallel lines of L17 L13; "d266" = 2 distance from line of L17.end L12; "d267" = 2 distance between parallel lines of L2 L21; "d268" = 2 distance from line of L1 L20.end
feature "Лофт1" sketch "Эскиз44" dims "d269" = 0, "d270" = 90 deg, "d271" = 0, "d272" = 90 deg
sketch "Эскиз45"
  geometry: L1 (86, -2.572)-(74.98, 0) reference; L2 (74.98, 0)-(0, 0) reference; L3 (0, 0)-(-59.708, -11.573) reference; L4 (-59.708, -11.573)-(-59.708, -98.573) reference; L5 (-59.708, -98.573)-(0, -110.145) reference; L6 (0, -110.145)-(74.98, -110.145) reference; L7 (74.98, -110.145)-(86, -107.572) reference; L8 (86, -107.572)-(86, -2.572) reference; L9 (-57.708, -12.572)-(-2.708, -12.572); L10 (-2.708, -12.572)-(-2.708, -97.572); L11 (-2.708, -97.572)-(-57.708, -97.572); L12 (-57.708, -97.572)-(-57.708, -12.572); L13 (84, -3.572)-(0, -3.572); L14 (0, -3.572)-(0, -106.572); L15 (0, -106.572)-(84, -106.572); L16 (84, -106.572)-(84, -3.572); L17 (86, -107.572)-(86, -2.572) reference; 5 further points
  constraints: 16 end point, 4 midpoint, 4 parallel, 2 horizontal, 2 horizontal alignment, 2 perpendicular
  dimensions: "d273" = 55 distance of L10.end L11.end; "d274" = 85 distance of L9.end L10.end; "d275" = 2 distance between parallel lines of L12 L4; "d276" = 84 distance of L15.end L14.end; "d277" = 103 distance of L14.end L13.end; "d278" = 2 distance between parallel lines of L8 L16
extrude "Выдавливание35" join sketch "Эскиз45" distance "d279" = 5; taper "d280" = 0 deg
sketch "Эскиз46"
  geometry: L1 (64.78, 115.427)-(64.78, 124.427) reference; L2 (64.78, 124.427)-(45.18, 124.427) reference; L3 (45.18, 124.427)-(45.18, 120.427) reference; L4 (29.8, 120.427)-(45.18, 120.427) reference; L5 (29.8, 120.427)-(29.8, 124.427) reference; L6 (29.8, 124.427)-(10.2, 124.427) reference; L7 (10.2, 124.427)-(10.2, 120.427) reference; L8 (0, 120.427)-(10.2, 120.427) reference; L9 (0, 120.427)-(0, -107.573) reference; L10 (0, -107.573)-(10.2, -107.573) reference; L11 (10.2, -107.573)-(10.2, -111.573) reference; L12 (10.2, -111.573)-(29.8, -111.573) reference; L13 (29.8, -111.573)-(29.8, -107.573) reference; L14 (29.8, -107.573)-(45.18, -107.573) reference; L15 (45.18, -107.573)-(45.18, -111.573) reference; L16 (45.18, -111.573)-(64.78, -111.573) reference; L17 (64.78, -111.573)-(64.78, -102.573) reference; L18 (64.78, -102.573)-(74.98, -102.573) reference; L19 (74.98, 115.427)-(74.98, -102.573) reference; L20 (74.98, 115.427)-(64.78, 115.427) reference; L21 (35.29, 66.61)-(35.29, 85.427) reference; L22 (35.29, 85.427)-(39.69, 85.427) reference; L23 (39.69, 85.427)-(39.69, 45.427) reference; L24 (39.69, 45.427)-(35.29, 45.427) reference; L25 (35.29, 45.427)-(35.29, 64.245) reference; L26 (35.29, -13.573)-(35.29, 26.427) reference; L27 (35.29, 26.427)-(39.69, 26.427) reference; L28 (39.69, 26.427)-(39.69, -13.573) reference; L29 (39.69, -13.573)-(35.29, -13.573) reference; L30 (39.69, -72.573)-(35.29, -72.573) reference; L31 (35.29, -72.573)-(35.29, -32.573) reference; L32 (35.29, -32.573)-(39.69, -32.573) reference; L33 (39.69, -32.573)-(39.69, -72.573) reference; L34 (37.49, -35.223)-(37.49, -69.923); C1 r 3.65 at (37.49, -93.573) reference; C2 r 3.65 at (62.08, 106.427) reference; C3 r 3.65 at (12.9, 106.427) reference; C4 r 1.75 at (6, 29.572) reference; C5 r 1.75 at (6, 65.427) reference; C6 r 1.75 at (34, 29.572) reference; C7 r 3.65 at (37.49, 106.427) reference; C8 r 3.65 at (12.9, -93.573) reference; C9 r 3.65 at (62.08, -93.573) reference; C10 r 1.65 at (37.49, -35.223); C11 r 1.65 at (37.49, -69.923); A1 r 1.75 centre (34, 65.427) between (35.29, 66.61) and (35.29, 64.245) reference; 4 further points
  constraints: 3 midpoint, 2 centre point, 2 end point, 1 coincident, 1 equal radius, 1 horizontal alignment, 1 vertical, 1 vertical alignment
  dimensions: "d281" = 3.3 diameter of C11; "d282" = 1 distance edge to line of C10 L32
extrude "Выдавливание36" cut sketch "Эскиз46" distance "d283" = 10; taper "d284" = 0 deg
fillet "Сопряжение7" dims "d285" = 2
chamfer "Фаска14" distance "d286" = 2.5; stored, may be unused: second distance "d287" = 2, angle "d288" = 45 deg
fillet "Сопряжение8" dims "d289" = 4
feature "ཐ耀དྷ耀པ耀བ耀མ耀ཚ耀ཛྷ耀ཞ耀" dims "d0" = 16, "d1" = 200, "d2" = 200, "d3" = 0, "d4" = 24.6, "d5" = 11, "d6" = 0, "d7" = 8, "d8" = 6, "d9" = 0, "d10" = 4, "d11" = 0, "d12" = 2.5, "d13" = 2.5 (= d12), "d14" = 3.2 (derived), "d15" = 3.2 (derived), "d16" = 3.2, "d17" = 5, "d18" = 0, "d19" = 5, "d20" = 2, "d21" = 2, "d22" = 45 deg, "d23" = 5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
node "Твердое тело1"
node "Твердое тело2"
node "Спроецированная петля1"
node "Спроецированная петля2"
node "Спроецированная петля3"
node "Спроецированная петля4"
node "Каретка"
node "Спроецированная петля8"
node "Рука"
node "Спроецированная петля10"
node "Основная плита"
node "Крепление"
node "Спроецированная петля12"
node "Спроецированная петля13"
node "Эскиз — прямоугольный массив1" dims "d85" = 24.58984 (derived), "d88" = 10
node "Спроецированная петля14"
node "Эскиз — прямоугольный массив2" dims "d101" = 24.58984 (derived), "d104" = 10
node "Спроецированная петля15"
node "Эскиз — прямоугольный массив3" dims "d116" = 59 (derived), "d119" = 10
node "Спроецированная петля16"
node "Ребро жесткости"
node "Спроецированная петля17"
node "Спроецированная петля18"
node "Спроецированная петля19"
node "Спроецированная петля20"
node "Спроецированная петля21"
node "Спроецированная петля22"
node "Эскиз — прямоугольный массив4" dims "d172" = 24.58984 (derived), "d175" = 10
node "Спроецированная петля23"
node "Спроецированная петля24"
node "Спроецированная петля25"
node "Спроецированная петля26"
node "Спроецированная петля27"
node "Спроецированная петля28"
node "Спроецированная петля29"
node "Спроецированная петля30"
node "Спроецированная петля31"
node "Спроецированная петля32"
node "Спроецированная петля33"
node "Стойки под колеса"
node "Колеса"
node "Эскиз — прямоугольный массив5" dims "d244" = 35.855 (derived), "d247" = 28 (derived)
node "Твердое тело13"
node "Спроецированная петля34"
node "Спроецированная петля35"
